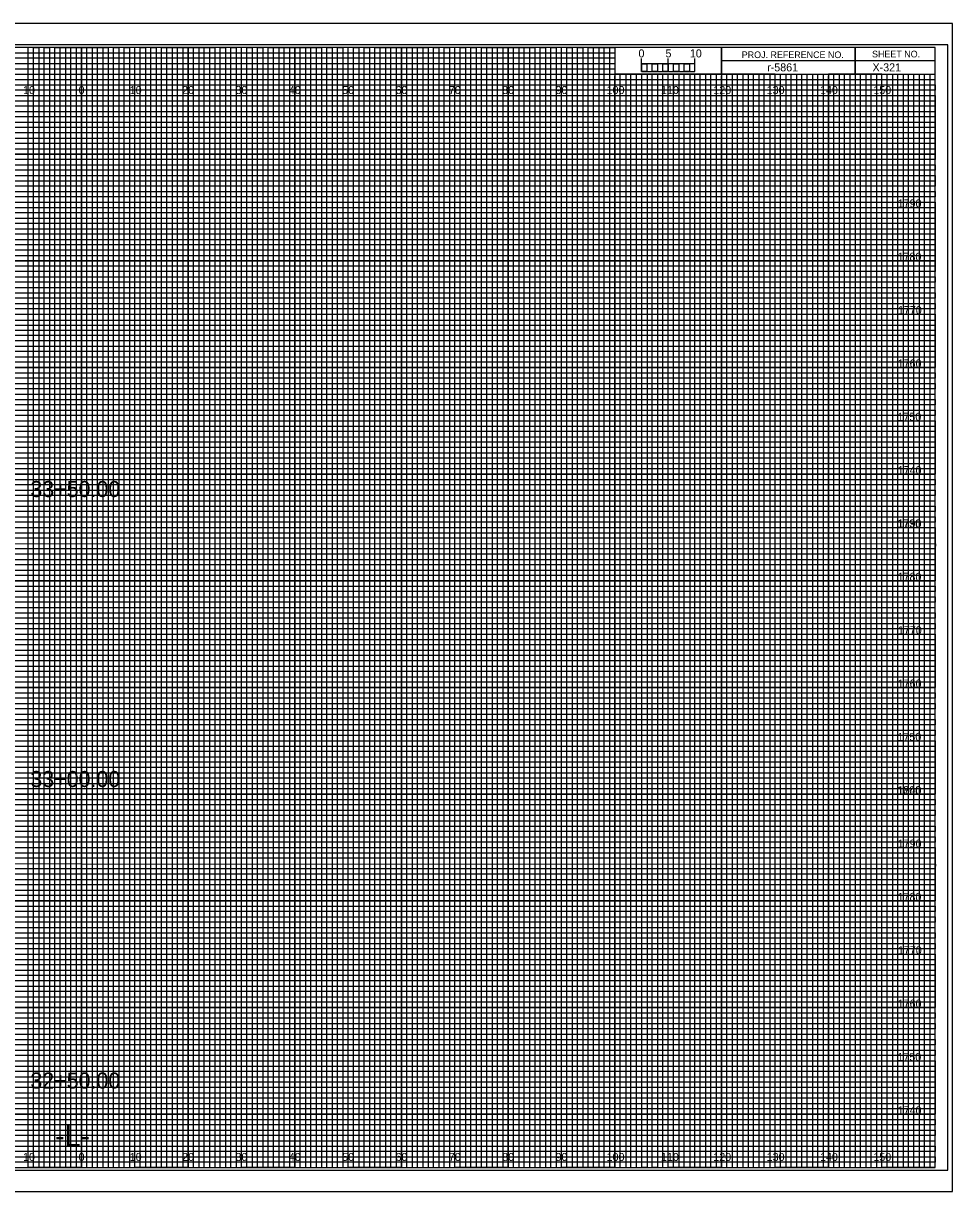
# Model space of a CAD drawing. Extents: x -15 to 323, y -5 to 6170.
# Drawn here: x 149.1 to 323.3, y 3735.5 to 3954.5 of the extents above; entities that cross this region are included whole.
import ezdxf

# ---------------------------------------------------------------- set-up
doc = ezdxf.new("R2010")
doc.units = 0
for name, color, linetype in [('Prop XS Alignment Label', 7, 'Continuous'), ('Prop XS Bar Scale Labels', 7, 'Continuous'), ('Prop XS DDE', 7, 'Continuous'), ('Prop XS DDE Earthwork Shape', 7, 'Continuous'), ('Prop XS DDE Slope Text', 7, 'Continuous'), ('Prop XS DDE Text', 7, 'Continuous'), ('Prop XS Earthwork Shape', 7, 'Continuous'), ('Prop XS Noise Wall', 7, 'Continuous'), ('Prop XS Project Number', 7, 'Continuous'), ('Prop XS Retaining Wall', 7, 'Continuous'), ('Prop XS Station Labels', 7, 'Continuous'), ('Prop XS Temporary Shoring', 7, 'Continuous'), ('Scratch_Level_3', 7, 'Continuous'), ('Scratch_Level_7', 7, 'Continuous'), ('Scratch_Level_8', 7, 'Continuous'), ('Sheet Cross Section Grid Minor 1 CELL', 7, 'Continuous')]:
    doc.layers.add(name, color=color, linetype=linetype)

msp = doc.modelspace()

# ---------------------------------------------------------------- linework, layer by layer
at = {"layer": 'Prop XS Alignment Label'}
for p, q in [((265, 3945.49), (265, 3947.9)), ((265, 3946.9), (265, 3947.9)), ((270, 3945.49), (270, 3947.9)), ((275, 3945.49), (275, 3947.9)), ((275, 3946.9), (275, 3947.9))]:
    msp.add_line(p, q, dxfattribs=at)
for points in [[(275, 3946.9), (265, 3946.9), (265, 3945.49), (275, 3945.49)], [(265, 3946.9), (266, 3946.9), (266, 3945.49), (265, 3945.49)], [(267, 3946.9), (268, 3946.9), (268, 3945.49), (267, 3945.49)], [(269, 3946.9), (270, 3946.9), (270, 3945.49), (269, 3945.49)], [(271, 3946.9), (272, 3946.9), (272, 3945.49), (271, 3945.49)], [(273, 3946.9), (274, 3946.9), (274, 3945.49), (273, 3945.49)]]:
    msp.add_lwpolyline(points, close=True, dxfattribs=at)
at = {"layer": 'Prop XS DDE'}
msp.add_lwpolyline([(-13.4, 3735.5), (323.3, 3735.5), (323.3, 3954.5), (-13.4, 3954.5)], close=True, dxfattribs=at)
at = {"layer": 'Prop XS DDE Slope Text'}
msp.add_lwpolyline([(-10.8, 3739.5), (322.4, 3739.5), (322.4, 3950.5), (-10.8, 3950.5)], close=True, dxfattribs=at)
at = {"layer": 'Prop XS DDE Text'}
for p, q in [((150, 3740), (150, 3950)), ((160, 3740), (160, 3950)), ((170, 3740), (170, 3950)), ((180, 3740), (180, 3950)), ((190, 3740), (190, 3950)), ((200, 3740), (200, 3950)), ((210, 3740), (210, 3950)), ((220, 3740), (220, 3950)), ((230, 3740), (230, 3950)), ((240, 3740), (240, 3950)), ((250, 3740), (250, 3950)), ((260, 3740), (260, 3944.69)), ((270, 3740), (270, 3944.69)), ((280, 3740), (280, 3944.69)), ((290, 3740), (290, 3944.69)), ((300, 3740), (300, 3944.69)), ((310, 3740), (310, 3944.69)), ((0, 3940), (320, 3940)), ((0, 3930), (320, 3930)), ((0, 3920), (320, 3920)), ((0, 3910), (320, 3910)), ((0, 3900), (320, 3900)), ((0, 3890), (320, 3890)), ((0, 3880), (320, 3880)), ((0, 3870), (320, 3870)), ((0, 3860), (320, 3860)), ((0, 3850), (320, 3850)), ((0, 3840), (320, 3840)), ((0, 3830), (320, 3830)), ((0, 3820), (320, 3820)), ((0, 3810), (320, 3810)), ((0, 3800), (320, 3800)), ((0, 3790), (320, 3790)), ((0, 3780), (320, 3780)), ((0, 3770), (320, 3770)), ((0, 3760), (320, 3760)), ((0, 3750), (320, 3750))]:
    msp.add_line(p, q, dxfattribs=at)
at = {"layer": 'Prop XS Earthwork Shape'}
for p, q in [((150, 3950), (140, 3950)), ((150, 3740), (150, 3950)), ((170, 3950), (160, 3950)), ((160, 3950), (160, 3740)), ((170, 3740), (170, 3950)), ((190, 3950), (180, 3950)), ((180, 3950), (180, 3740)), ((190, 3740), (190, 3950)), ((210, 3950), (200, 3950)), ((200, 3950), (200, 3740)), ((210, 3740), (210, 3950)), ((230, 3950), (220, 3950)), ((220, 3950), (220, 3740)), ((230, 3740), (230, 3950)), ((250, 3950), (240, 3950)), ((240, 3950), (240, 3740)), ((250, 3740), (250, 3950)), ((260, 3950), (260, 3740)), ((270, 3740), (270, 3945)), ((290, 3945), (280, 3945)), ((280, 3945), (280, 3740)), ((290, 3740), (290, 3945)), ((310, 3945), (300, 3945)), ((300, 3945), (300, 3740)), ((310, 3740), (310, 3945)), ((160, 3740), (150, 3740)), ((180, 3740), (170, 3740)), ((200, 3740), (190, 3740)), ((220, 3740), (210, 3740)), ((240, 3740), (230, 3740)), ((260, 3740), (250, 3740)), ((280, 3740), (270, 3740)), ((300, 3740), (290, 3740)), ((320, 3740), (310, 3740)), ((320, 3740), (320, 3740))]:
    msp.add_line(p, q, dxfattribs=at)
for points in [[(0, 3940), (320, 3940), (320, 3930), (0, 3930)], [(0, 3920), (320, 3920), (320, 3910), (0, 3910)], [(0, 3900), (320, 3900), (320, 3890), (0, 3890)], [(0, 3880), (320, 3880), (320, 3870), (0, 3870)], [(0, 3860), (320, 3860), (320, 3850), (0, 3850)], [(0, 3840), (320, 3840), (320, 3830), (0, 3830)], [(0, 3820), (320, 3820), (320, 3810), (0, 3810)], [(0, 3800), (320, 3800), (320, 3790), (0, 3790)], [(0, 3780), (320, 3780), (320, 3770), (0, 3770)], [(0, 3760), (320, 3760), (320, 3750), (0, 3750)]]:
    msp.add_lwpolyline(points, dxfattribs=at)
at = {"layer": 'Prop XS Noise Wall'}
for p, q in [((305, 3950), (305, 3945)), ((305, 3945), (305, 3950)), ((280, 3947.5), (280, 3945)), ((320, 3947.49), (280, 3947.49)), ((280, 3945), (320, 3945))]:
    msp.add_line(p, q, dxfattribs=at)
for points in [[(320, 3950), (0, 3950), (0, 3740), (320, 3740)], [(280, 3950), (260, 3950), (260, 3945.03), (280, 3945.03)], [(320, 3950), (280, 3950), (280, 3945), (320, 3945)]]:
    msp.add_lwpolyline(points, close=True, dxfattribs=at)
at = {"layer": 'Prop XS Retaining Wall'}
for p, q in [((267, 3945), (266.01, 3945)), ((266.01, 3945), (266.01, 3740)), ((267, 3740), (267, 3945)), ((269, 3945), (268, 3945)), ((268, 3945), (268, 3740)), ((269, 3740), (269, 3945)), ((266.01, 3740), (265, 3740)), ((268, 3740), (267, 3740))]:
    msp.add_line(p, q, dxfattribs=at)
for points in [[(150, 3740), (151, 3740), (151, 3950), (152, 3950), (152, 3740)], [(152, 3740), (153, 3740), (153, 3950), (154, 3950), (154, 3740)], [(155, 3740), (156, 3740), (156, 3950), (157, 3950), (157, 3740)], [(157, 3740), (158, 3740), (158, 3950), (159, 3950), (159, 3740)], [(160, 3740), (161, 3740), (161, 3950), (162, 3950), (162, 3740)], [(162, 3740), (163, 3740), (163, 3950), (164, 3950), (164, 3740)], [(165, 3740), (166, 3740), (166, 3950), (167, 3950), (167, 3740)], [(167, 3740), (168, 3740), (168, 3950), (169, 3950), (169, 3740)], [(170, 3740), (171, 3740), (171, 3950), (172, 3950), (172, 3740)], [(172, 3740), (173, 3740), (173, 3950), (174, 3950), (174, 3740)], [(175, 3740), (176, 3740), (176, 3950), (177, 3950), (177, 3740)], [(177, 3740), (178, 3740), (178, 3950), (179, 3950), (179, 3740)], [(180, 3740), (181, 3740), (181, 3950), (182, 3950), (182, 3740)], [(182, 3740), (183, 3740), (183, 3950), (184, 3950), (184, 3740)], [(185, 3740), (186, 3740), (186, 3950), (187, 3950), (187, 3740)], [(187, 3740), (188, 3740), (188, 3950), (189, 3950), (189, 3740)], [(190, 3740), (191, 3740), (191, 3950), (192, 3950), (192, 3740)], [(192, 3740), (193, 3740), (193, 3950), (194, 3950), (194, 3740)], [(195, 3740), (196, 3740), (196, 3950), (197, 3950), (197, 3740)], [(197, 3740), (198, 3740), (198, 3950), (199, 3950), (199, 3740)], [(200, 3740), (201, 3740), (201, 3950), (202, 3950), (202, 3740)], [(202, 3740), (203, 3740), (203, 3950), (204, 3950), (204, 3740)], [(205, 3740), (206, 3740), (206, 3950), (207, 3950), (207, 3740)], [(207, 3740), (208, 3740), (208, 3950), (209, 3950), (209, 3740)], [(210, 3740), (211, 3740), (211, 3950), (212, 3950), (212, 3740)], [(212, 3740), (213, 3740), (213, 3950), (214, 3950), (214, 3740)], [(215, 3740), (216, 3740), (216, 3950), (217, 3950), (217, 3740)], [(217, 3740), (218, 3740), (218, 3950), (219, 3950), (219, 3740)], [(220, 3740), (221, 3740), (221, 3950), (222, 3950), (222, 3740)], [(222, 3740), (223, 3740), (223, 3950), (224, 3950), (224, 3740)], [(225, 3740), (226, 3740), (226, 3950), (227, 3950), (227, 3740)], [(227, 3740), (228, 3740), (228, 3950), (229, 3950), (229, 3740)], [(230, 3740), (231, 3740), (231, 3950), (232, 3950), (232, 3740)], [(232, 3740), (233, 3740), (233, 3950), (234, 3950), (234, 3740)], [(235, 3740), (236, 3740), (236, 3950), (237, 3950), (237, 3740)], [(237, 3740), (238, 3740), (238, 3950), (239, 3950), (239, 3740)], [(240, 3740), (241, 3740), (241, 3950), (242, 3950), (242, 3740)], [(242, 3740), (243, 3740), (243, 3950), (244, 3950), (244, 3740)], [(245, 3740), (246, 3740), (246, 3950), (247, 3950), (247, 3740)], [(247, 3740), (248, 3740), (248, 3950), (249, 3950), (249, 3740)], [(250, 3740), (251, 3740), (251, 3950), (252, 3950), (252, 3740)], [(252, 3740), (253, 3740), (253, 3950), (254, 3950), (254, 3740)], [(255, 3740), (256, 3740), (256, 3950), (257, 3950), (257, 3740)], [(257, 3740), (258, 3740), (258, 3950), (259, 3950), (259, 3740)], [(260, 3740), (261, 3740), (261, 3945), (262.02, 3945), (262.02, 3740)], [(262, 3740), (263, 3740), (263, 3945), (263.99, 3945), (263.99, 3740)], [(270, 3740), (270.98, 3740), (270.98, 3945), (272, 3945), (272, 3740)], [(272, 3740), (273, 3740), (273, 3945), (274.05, 3945), (274.05, 3740)], [(275, 3740), (276, 3740), (276, 3945), (277, 3945), (277, 3740)], [(277, 3740), (278, 3740), (278, 3945), (279, 3945), (279, 3740)], [(280, 3740), (281, 3740), (281, 3945), (282, 3945), (282, 3740)], [(282, 3740), (283, 3740), (283, 3945), (284, 3945), (284, 3740)], [(285, 3740), (286, 3740), (286, 3945), (287, 3945), (287, 3740)], [(287, 3740), (288, 3740), (288, 3945), (289, 3945), (289, 3740)], [(290, 3740), (291, 3740), (291, 3945), (292, 3945), (292, 3740)], [(292, 3740), (293, 3740), (293, 3945), (294, 3945), (294, 3740)], [(295, 3740), (296, 3740), (296, 3945), (297, 3945), (297, 3740)], [(297, 3740), (298, 3740), (298, 3945), (299, 3945), (299, 3740)], [(300, 3740), (301, 3740), (301, 3945), (302, 3945), (302, 3740)], [(302, 3740), (303, 3740), (303, 3945), (304, 3945), (304, 3740)], [(305, 3740), (306, 3740), (306, 3945), (307, 3945), (307, 3740)], [(307, 3740), (308, 3740), (308, 3945), (309, 3945), (309, 3740)], [(310, 3740), (311, 3740), (311, 3945), (312, 3945), (312, 3740)], [(312, 3740), (313, 3740), (313, 3945), (314, 3945), (314, 3740)], [(315, 3740), (316, 3740), (316, 3945), (317, 3945), (317, 3740)], [(317, 3740), (318, 3740), (318, 3945), (319, 3945), (319, 3740)]]:
    msp.add_lwpolyline(points, dxfattribs=at)
at = {"layer": 'Prop XS Station Labels'}
for points in [[(145, 3740), (155, 3740), (155, 3950), (165, 3950), (165, 3740), (175, 3740), (175, 3950), (185, 3950), (185, 3740), (195, 3740), (195, 3950), (205, 3950), (205, 3740), (215, 3740), (215, 3950), (225, 3950), (225, 3740), (235, 3740), (235, 3950), (245, 3950), (245, 3740), (255, 3740), (255, 3950), (259.93, 3950), (260, 3950), (260, 3945), (264.99, 3945), (264.99, 3740), (275, 3740), (275, 3945), (285, 3945), (285, 3740), (295, 3740), (295, 3945), (305, 3945), (305, 3740), (315, 3740), (315, 3945)], [(0, 3945), (275, 3945)], [(0, 3925), (320, 3925), (320, 3935), (0, 3935)], [(0, 3905), (320, 3905), (320, 3915), (0, 3915)], [(0, 3885), (320, 3885), (320, 3895), (0, 3895)], [(0, 3865), (320, 3865), (320, 3875), (0, 3875)], [(0, 3845), (320, 3845), (320, 3855), (0, 3855)], [(0, 3825), (320, 3825), (320, 3835), (0, 3835)], [(0, 3805), (320, 3805), (320, 3815), (0, 3815)], [(0, 3785), (320, 3785), (320, 3795), (0, 3795)], [(0, 3765), (320, 3765), (320, 3775), (0, 3775)], [(0, 3745), (320, 3745), (320, 3755), (0, 3755)]]:
    msp.add_lwpolyline(points, dxfattribs=at)
at = {"layer": 'Scratch_Level_7'}
for p, q in [((323.3, 3954.5), (-13.4, 3954.5)), ((-13.4, 3735.5), (323.3, 3735.5))]:
    msp.add_line(p, q, dxfattribs=at)
at = {"layer": 'Sheet Cross Section Grid Minor 1 CELL'}
for p, q in [((0, 3949), (260, 3949)), ((260, 3949), (260, 3947.98)), ((260, 3947.98), (0, 3947.98)), ((0, 3947), (260, 3947)), ((260, 3947), (260, 3945.89)), ((260, 3945.89), (0, 3945.89)), ((0, 3944), (320, 3944))]:
    msp.add_line(p, q, dxfattribs=at)
for points in [[(0, 3943), (270, 3943), (320, 3943), (320, 3942), (0, 3942)], [(0, 3941), (320, 3941), (320, 3939), (0, 3939)], [(0, 3938), (320, 3938), (320, 3937), (0, 3936.98)], [(0, 3936), (320, 3936), (320, 3934), (0, 3934)], [(0, 3933), (320, 3933), (320, 3932), (0, 3932)], [(0, 3931), (320, 3931), (320, 3929), (0, 3929)], [(0, 3928), (320, 3928), (320, 3927), (0, 3927)], [(0, 3926), (320, 3926), (320, 3924), (0, 3924)], [(0, 3923), (320, 3923), (320, 3922), (0, 3922)], [(0, 3921), (320, 3921), (320, 3919), (0, 3919)], [(0, 3918), (320, 3918), (320, 3917), (0, 3917)], [(0, 3916), (320, 3916), (320, 3913.95), (320, 3913), (320, 3912), (0, 3912)], [(0, 3914), (320, 3914), (320, 3913), (0, 3913)], [(0, 3911), (320, 3911), (320, 3909), (0, 3909.03)], [(0, 3909.03), (320, 3909), (320, 3908), (0, 3908)], [(0, 3907), (320, 3907), (320, 3906), (0, 3906)], [(0, 3904), (320, 3904), (320, 3903), (0, 3903)], [(0, 3902), (320, 3902), (320, 3901), (0, 3901)], [(-0.07, 3898.89), (320, 3898.89), (320, 3897.88), (-0.07, 3897.88)], [(0, 3897), (320, 3897), (320, 3896), (0, 3896)], [(0, 3894), (320, 3894), (320, 3893), (0, 3893)], [(0, 3892), (320, 3892), (320, 3891), (0, 3891)], [(0, 3889), (320, 3889), (320, 3888), (0, 3888)], [(0, 3887), (320, 3887), (320, 3886), (0, 3886)], [(0, 3884), (320, 3884), (320, 3883), (0, 3883)], [(0, 3882), (320, 3882), (320, 3881), (0, 3881)], [(0, 3879), (320, 3879), (319.99, 3877.98), (0, 3878)], [(0, 3877), (320, 3877), (320, 3876), (0, 3876)], [(0, 3874), (320, 3874), (320, 3873), (0, 3873)], [(0, 3872), (320, 3872), (320, 3871), (0, 3871)], [(0, 3869), (320, 3869), (320, 3868), (0, 3868)], [(0, 3867), (320, 3867), (320, 3866), (0, 3866)], [(0, 3864), (320, 3864), (320, 3863), (0, 3863)], [(0, 3862), (320, 3862), (320, 3861), (0, 3861)], [(0, 3859), (320, 3859), (320, 3858), (0, 3858)], [(0, 3856.99), (320.07, 3856.91), (320, 3856), (0, 3856)], [(0, 3854), (320, 3854), (320, 3853), (0, 3853)], [(0, 3852), (320, 3852), (320, 3851), (0, 3851)], [(0, 3849), (320, 3849), (320, 3848), (0, 3848)], [(0, 3847), (320, 3847), (320, 3846), (0, 3846)], [(0, 3844), (320, 3844), (320, 3843), (0, 3843)], [(0, 3842), (320, 3842), (320, 3841), (0, 3841)], [(0, 3839), (320, 3839), (320, 3838), (0, 3838)], [(0, 3837), (320, 3837), (320, 3836), (0, 3836)], [(0, 3834), (320, 3834), (320, 3833), (0, 3833)], [(0, 3832), (320, 3832), (320, 3831), (0, 3831)], [(0, 3829), (320, 3829), (320, 3828), (0, 3828)], [(0, 3827), (320, 3827), (320, 3826), (0, 3826)], [(0, 3824), (320, 3824), (320, 3823), (0, 3823)], [(0, 3822), (320, 3822), (320, 3821), (0, 3821)], [(0, 3819), (320, 3819), (319.99, 3817.98), (0, 3818)], [(0, 3817), (320, 3817), (320, 3816), (0, 3816)], [(0, 3814), (320, 3814), (320, 3813), (0, 3813)], [(0, 3812), (320, 3812), (320, 3811), (0, 3811)], [(0, 3809), (320, 3809), (320, 3808), (0, 3808)], [(0, 3807), (320, 3807), (320, 3806), (0, 3806)], [(0, 3804), (320, 3804), (320, 3803), (0, 3803)], [(0, 3802), (320, 3802), (320, 3801), (0, 3801)], [(0, 3799), (320, 3799), (320, 3798), (0, 3798)], [(0, 3796.99), (320.07, 3796.91), (320, 3796), (0, 3796)], [(0, 3794), (320, 3794), (320, 3793), (0, 3793)], [(0, 3792), (320, 3792), (320, 3791), (0, 3791)], [(0, 3789), (320, 3789), (320, 3788), (0, 3788)], [(0, 3787), (320, 3787), (320, 3786), (0, 3786)], [(0, 3784), (320, 3784), (320, 3783), (0, 3783)], [(0, 3782), (320, 3782), (320, 3781), (0, 3781)], [(0, 3779), (320, 3779), (320, 3778), (0, 3778)], [(0, 3777), (320, 3777), (320, 3776), (0, 3776)], [(0, 3774), (320, 3774), (320, 3773), (0, 3773)], [(0, 3772), (320, 3772), (320, 3771), (0, 3771)], [(0, 3769), (320, 3769), (320, 3768), (0, 3768)], [(0, 3767), (320, 3767), (320, 3766), (0, 3766)], [(0, 3764), (320, 3764), (320, 3763), (0, 3763)], [(0, 3762), (320, 3762), (320, 3761), (0, 3761)], [(0, 3759), (320, 3759), (320, 3758), (0, 3758)], [(0, 3757), (320, 3757), (320, 3756), (0, 3756)], [(0, 3754), (320, 3754), (320, 3753), (0, 3753)], [(0, 3752), (320, 3752), (320, 3751), (0, 3751)], [(0, 3749), (320, 3749), (320, 3748), (0, 3748)], [(0, 3747), (320, 3747), (320, 3746), (0, 3746)], [(0, 3744), (320, 3744), (320, 3743), (0, 3743)], [(0, 3742), (320, 3742), (320, 3741), (0, 3741)]]:
    msp.add_lwpolyline(points, dxfattribs=at)

# ---------------------------------------------------------------- texts
at = {"layer": 'Prop XS Alignment Label'}
for s, height, p in [('0', 1.5, (264.41, 3948.12)), ('-L-', 4, (155.06, 3744))]:
    msp.add_text(s, height=height, dxfattribs=at).set_placement(p)
at = {"layer": 'Prop XS Bar Scale Labels'}
for s, p in [('5', (269.47, 3948.12)), ('10', (274.04, 3948.12))]:
    msp.add_text(s, height=1.5, dxfattribs=at).set_placement(p)
at = {"layer": 'Prop XS DDE Earthwork Shape'}
msp.add_text('X-321', height=1.5, dxfattribs=at).set_placement((308.28, 3945.5))
at = {"layer": 'Prop XS Noise Wall'}
for s, p in [('PROJ. REFERENCE NO.', (283.77, 3947.99)), ('SHEET NO.', (308.19, 3948.12))]:
    msp.add_text(s, height=1.25, dxfattribs=at).set_placement(p)
at = {"layer": 'Prop XS Project Number'}
msp.add_text('r-5861', height=1.5, dxfattribs=at).set_placement((288.53, 3945.5))
at = {"layer": 'Prop XS Temporary Shoring'}
for s, p in [('33+50.00', (150.41, 3865.71)), ('33+00.00', (150.41, 3811.35)), ('32+50.00', (150.41, 3754.83))]:
    msp.add_text(s, height=3, dxfattribs=at).set_placement(p)
at = {"layer": 'Scratch_Level_3'}
for s, p in [('1790', (313, 3920)), ('1780', (312.98, 3910)), ('1770', (313.04, 3900)), ('1760', (313, 3890)), ('1750', (312.96, 3880)), ('1740', (313, 3870)), ('1730', (312.92, 3860)), ('1790', (313, 3860)), ('1780', (312.98, 3850)), ('1770', (313.04, 3840)), ('1760', (313, 3830)), ('1750', (312.96, 3820)), ('1800', (312.92, 3810)), ('1740', (313, 3810)), ('1790', (313, 3800)), ('1780', (312.98, 3790)), ('1770', (313.04, 3780)), ('1760', (313, 3770)), ('1750', (312.96, 3760)), ('1740', (313, 3750))]:
    msp.add_text(s, height=1.5, dxfattribs=at).set_placement(p)
at = {"layer": 'Scratch_Level_8'}
for s, p in [('10', (149.04, 3941.25)), ('0', (159.45, 3941.25)), ('0', (159.45, 3941.25)), ('10', (169.04, 3941.25)), ('20', (178.86, 3941.25)), ('30', (188.86, 3941.25)), ('40', (198.86, 3941.25)), ('50', (208.86, 3941.25)), ('60', (218.86, 3941.25)), ('70', (228.86, 3941.25)), ('80', (238.86, 3941.25)), ('90', (248.86, 3941.25)), ('100', (258.44, 3941.25)), ('110', (268.62, 3941.25)), ('120', (278.44, 3941.25)), ('130', (288.44, 3941.25)), ('140', (298.44, 3941.25)), ('150', (308.44, 3941.25)), ('10', (149.04, 3741.25)), ('0', (159.45, 3741.25)), ('0', (159.45, 3741.25)), ('10', (169.04, 3741.25)), ('20', (178.86, 3741.25)), ('30', (188.86, 3741.25)), ('40', (198.86, 3741.25)), ('50', (208.86, 3741.25)), ('60', (218.86, 3741.25)), ('70', (228.86, 3741.25)), ('80', (238.86, 3741.25)), ('90', (248.86, 3741.25)), ('100', (258.44, 3741.25)), ('110', (268.62, 3741.25)), ('120', (278.44, 3741.25)), ('130', (288.44, 3741.25)), ('140', (298.44, 3741.25)), ('150', (308.44, 3741.25))]:
    msp.add_text(s, height=1.5, dxfattribs=at).set_placement(p)

doc.saveas('drawing.dxf')
